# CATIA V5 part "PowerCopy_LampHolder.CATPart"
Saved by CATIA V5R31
Part number: LampHolder
Bounding box of the stored display mesh (mm): x -25 to 25, y -5 to 5, z -5 to 25
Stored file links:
  C:\Users\patol451\OneDrive - Linköpings universitet\Nuvarande kurser\Exjobb\LampCATIA\PowerCopy_LampHolder.CATPart
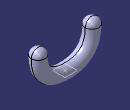
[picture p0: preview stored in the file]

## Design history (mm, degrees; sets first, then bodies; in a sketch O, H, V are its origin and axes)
Parameters
  diameter = 10 mm
Set1 "References"
  Plane1 "xy": type Offset, RefPlane xy-plane, Offset 0
  Point1 "P1": (0, 0, 0)
  Point2 "PLeft": (-20, 0, 20)
  Point3 "PRight": (20, 0, 20)
Set2 "Placement"
  Point4 "PlacementPoint": (0, 0, 0), relative to Point1
Set3 "Output"
  Point5 "OutputPoint1": (0, 0, 0), relative to Point3
Set4 "Geo_1"
  Curve1: Elements (Point2; Point1; Point3)
  Circle1: type CtrRad, Start 0, End 180, Center {project ToProject Point3, Support Plane3}, Support Plane1, Radius 5 {= diameter /2}, FirstDirection (1, 0, 0)
  Plane2: type OffsetPt, RefPlane Plane1, RefPoint Point3
  Plane3: type Offset, RefPlane Plane2, Offset 5 {= diameter /2}
  MultiSel1
  Line1: type PtPt, FirstPoint {project ToProject Point3, Support Plane3}, SecondPoint Point3
  Line2: type PtPt, FirstPoint {project ToProject Point2, Support Plane3}, SecondPoint Point2
  Join1: Elements (Line1; Curve1; Line2)
Body1 (main body)
  Rib1: profile Circle1, centre curve Join1
  Fillet1: radius 5 {= diameter /2}, on edge [face of Rib1 | face of Rib1] (x2)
